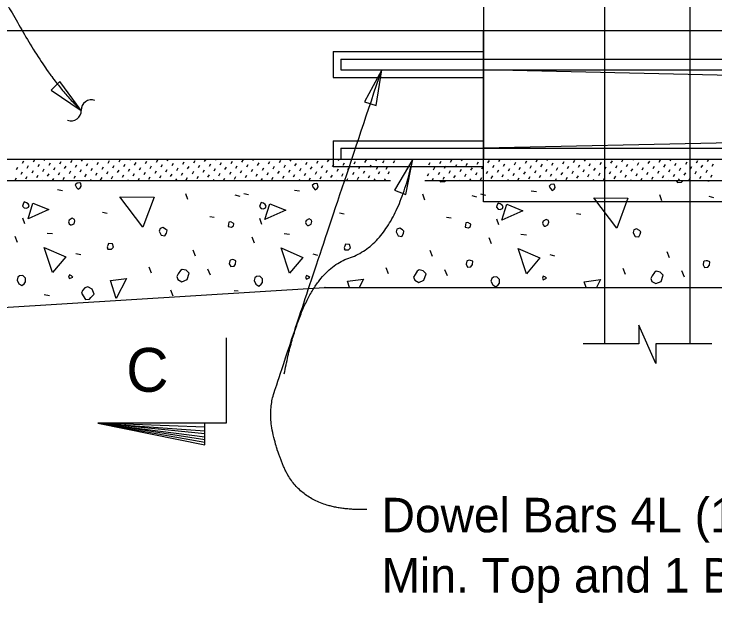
# Model space of a CAD drawing. Extents: x 1.5 to 68.7, y 0 to 31.
# Drawn here: x 28.879 to 32.972, y 9.338 to 12.779 of the extents above; entities that cross this region are included whole.
import ezdxf

# ---------------------------------------------------------------- set-up
doc = ezdxf.new("R2010")
doc.units = 0
for name, color, linetype in [('Dimension', 7, 'Continuous'), ('Miscellaneous', 7, 'Continuous'), ('Rebar', 7, 'Continuous'), ('TextStructures', 7, 'Continuous'), ('TrafBarrierConc', 7, 'Continuous')]:
    doc.layers.add(name, color=color, linetype=linetype)

msp = doc.modelspace()

# ---------------------------------------------------------------- linework, layer by layer
at = {"layer": 'Dimension'}
for p, q in [((29.9931, 10.3647), (29.3681, 10.3881)), ((29.3681, 10.3881), (29.9931, 10.3447)), ((29.9931, 10.3264), (29.3681, 10.3881)), ((29.3681, 10.3881), (29.9931, 10.3081)), ((29.9931, 10.2914), (29.3681, 10.3881)), ((29.3681, 10.3881), (29.9931, 10.2781))]:
    msp.add_line(p, q, dxfattribs=at)
for points in [[(31.0259, 12.4528), (30.9264, 12.2665), (30.9933, 12.2442)], [(29.2714, 12.2154), (29.1461, 12.3855), (29.0971, 12.3347)], [(31.2075, 11.932), (31.1012, 11.7494), (31.1672, 11.7246)]]:
    msp.add_lwpolyline(points, close=True, dxfattribs=at)
for points in [[(32.9524, 10.8531), (32.6271, 10.8531), (32.6271, 10.7369), (32.5277, 10.9619), (32.5277, 10.8531), (32.2024, 10.8531)], [(30.1181, 10.8881), (30.1181, 10.3881), (29.3681, 10.3881), (29.9931, 10.2631), (29.9931, 10.3881)]]:
    msp.add_lwpolyline(points, dxfattribs=at)
for centre, start, end in [((29.3316, 12.2178), 70.0924, 181.8197), ((29.2124, 12.214), 250.0924, 1.8197)]:
    msp.add_arc(centre, 0.0596, start, end, dxfattribs=at)
for points in [[(28.4708, 12.9203), (28.7034, 12.864), (28.7449, 13.0099), (29.089, 12.3912), (29.2714, 12.2154)], [(30.9383, 9.8847), (30.5669, 9.8722), (30.3433, 10.3915), (30.4451, 10.7169), (31.0259, 12.4528)], [(30.4572, 10.6771), (30.5703, 11.266), (31.1018, 11.4411), (31.2075, 11.932)]]:
    msp.add_open_spline(points, degree=2, dxfattribs=at)
at = {"layer": 'Miscellaneous'}
for p, q in [((28.9291, 11.907), (28.9372, 11.921)), ((28.9926, 11.9151), (29.0007, 11.9291)), ((29.0561, 11.9232), (29.0612, 11.932)), ((29.0838, 11.8955), (29.0919, 11.9095)), ((29.1196, 11.9313), (29.12, 11.932)), ((29.1473, 11.9036), (29.1554, 11.9176)), ((29.2107, 11.9117), (29.2188, 11.9257)), ((29.2742, 11.9198), (29.2813, 11.932)), ((29.3377, 11.9279), (29.3401, 11.932)), ((29.3654, 11.9002), (29.3735, 11.9142)), ((29.4289, 11.9083), (29.437, 11.9223)), ((29.4924, 11.9164), (29.5005, 11.9304)), ((29.5559, 11.9245), (29.5602, 11.932)), ((29.5836, 11.8968), (29.5917, 11.9108)), ((29.6471, 11.9049), (29.6552, 11.9189)), ((29.7106, 11.913), (29.7187, 11.927)), ((29.7741, 11.9211), (29.7804, 11.932)), ((29.8376, 11.9292), (29.8392, 11.932)), ((29.8653, 11.9015), (29.8734, 11.9155)), ((29.9288, 11.9096), (29.9369, 11.9236)), ((29.9922, 11.9177), (30.0003, 11.9317)), ((30.0557, 11.9258), (30.0593, 11.932)), ((30.0834, 11.8981), (30.0915, 11.9121)), ((30.1469, 11.9062), (30.155, 11.9202)), ((30.2104, 11.9143), (30.2185, 11.9283)), ((30.2739, 11.9224), (30.2794, 11.932)), ((30.3016, 11.8948), (30.3097, 11.9087)), ((30.3374, 11.9306), (30.3382, 11.932)), ((30.3651, 11.9029), (30.3732, 11.9169)), ((30.4286, 11.911), (30.4367, 11.925)), ((30.4921, 11.9191), (30.4996, 11.932)), ((30.5556, 11.9272), (30.5584, 11.932)), ((30.5833, 11.8995), (30.5914, 11.9135)), ((30.6468, 11.9076), (30.6549, 11.9216)), ((30.7103, 11.9157), (30.7184, 11.9297)), ((30.7737, 11.9238), (30.7785, 11.932)), ((30.8014, 11.8961), (30.8095, 11.9101)), ((30.8372, 11.9319), (30.8373, 11.932)), ((30.8649, 11.9042), (30.873, 11.9182)), ((30.9284, 11.9123), (30.9365, 11.9263)), ((30.9919, 11.9204), (30.9986, 11.932)), ((31.0331, 11.9089), (31.0412, 11.9229)), ((31.0554, 11.9285), (31.0574, 11.932)), ((31.0941, 11.9089), (31.1022, 11.9229)), ((31.3013, 11.8974), (31.3094, 11.9114)), ((31.3648, 11.9055), (31.3729, 11.9195)), ((31.4283, 11.9136), (31.4364, 11.9276)), ((31.4918, 11.9217), (31.4977, 11.932)), ((31.5552, 11.9298), (31.5565, 11.932)), ((31.5829, 11.9021), (31.591, 11.9161)), ((31.6464, 11.9102), (31.6545, 11.9242)), ((31.7099, 11.9183), (31.7178, 11.932)), ((31.7734, 11.9264), (31.7766, 11.932)), ((31.8011, 11.8987), (31.8092, 11.9127)), ((31.8646, 11.9068), (31.8727, 11.9208)), ((31.9281, 11.9149), (31.9362, 11.9289)), ((31.9916, 11.923), (31.9968, 11.932)), ((32.0193, 11.8953), (32.0274, 11.9093)), ((32.0551, 11.9311), (32.0556, 11.932)), ((32.0828, 11.9034), (32.0909, 11.9174)), ((32.1463, 11.9115), (32.1544, 11.9255)), ((32.2098, 11.9196), (32.2169, 11.932)), ((32.2733, 11.9278), (32.2757, 11.932)), ((32.301, 11.9001), (32.3091, 11.9141)), ((32.3644, 11.9082), (32.3725, 11.9222)), ((32.4279, 11.9163), (32.436, 11.9303)), ((32.4914, 11.9244), (32.4958, 11.932)), ((32.5191, 11.8967), (32.5272, 11.9107)), ((32.5826, 11.9048), (32.5907, 11.9188)), ((32.6461, 11.9129), (32.6542, 11.9269)), ((32.7096, 11.921), (32.716, 11.932)), ((32.7731, 11.9291), (32.7748, 11.932)), ((32.8008, 11.9014), (32.8089, 11.9154)), ((32.8643, 11.9095), (32.8724, 11.9235)), ((32.9278, 11.9176), (32.9359, 11.9316)), ((28.8933, 11.8712), (28.9014, 11.8852)), ((28.9568, 11.8793), (28.9649, 11.8933)), ((29.0203, 11.8874), (29.0284, 11.9014)), ((29.048, 11.8597), (29.0561, 11.8737)), ((29.1115, 11.8678), (29.1196, 11.8818)), ((29.1749, 11.8759), (29.1831, 11.8899)), ((29.2384, 11.884), (29.2465, 11.898)), ((29.2661, 11.8563), (29.2742, 11.8703)), ((29.3019, 11.8921), (29.31, 11.9061)), ((29.3296, 11.8644), (29.3377, 11.8784)), ((29.3931, 11.8725), (29.4012, 11.8865)), ((29.4566, 11.8806), (29.4647, 11.8946)), ((29.5201, 11.8887), (29.5282, 11.9027)), ((29.5478, 11.861), (29.5559, 11.875)), ((29.6113, 11.8691), (29.6194, 11.8831)), ((29.6748, 11.8772), (29.6829, 11.8912)), ((29.7383, 11.8853), (29.7464, 11.8993)), ((29.766, 11.8576), (29.7741, 11.8716)), ((29.8018, 11.8934), (29.8099, 11.9074)), ((29.8295, 11.8657), (29.8376, 11.8797)), ((29.893, 11.8738), (29.9011, 11.8878)), ((29.9564, 11.8819), (29.9646, 11.8959)), ((29.9841, 11.8542), (29.9922, 11.8682)), ((30.0199, 11.89), (30.028, 11.904)), ((30.0476, 11.8623), (30.0557, 11.8763)), ((30.1111, 11.8704), (30.1192, 11.8844)), ((30.1746, 11.8785), (30.1827, 11.8925)), ((30.2381, 11.8867), (30.2462, 11.9006)), ((30.2658, 11.859), (30.2739, 11.873)), ((30.3293, 11.8671), (30.3374, 11.8811)), ((30.3928, 11.8752), (30.4009, 11.8892)), ((30.4563, 11.8833), (30.4644, 11.8973)), ((30.484, 11.8556), (30.4921, 11.8696)), ((30.5198, 11.8914), (30.5279, 11.9054)), ((30.5475, 11.8637), (30.5556, 11.8777)), ((30.611, 11.8718), (30.6191, 11.8858)), ((30.6745, 11.8799), (30.6826, 11.8939)), ((30.7379, 11.888), (30.7461, 11.902)), ((30.7656, 11.8603), (30.7737, 11.8743)), ((30.8291, 11.8684), (30.8372, 11.8824)), ((30.8926, 11.8765), (30.9007, 11.8905)), ((30.9561, 11.8846), (30.9642, 11.8986)), ((30.9957, 11.8731), (31.0038, 11.8871)), ((31.0515, 11.8731), (31.0596, 11.8871)), ((31.329, 11.8697), (31.3371, 11.8837)), ((31.3925, 11.8778), (31.4006, 11.8918)), ((31.456, 11.8859), (31.4641, 11.8999)), ((31.4837, 11.8582), (31.4918, 11.8722)), ((31.5195, 11.894), (31.5276, 11.908)), ((31.5471, 11.8663), (31.5552, 11.8803)), ((31.6106, 11.8744), (31.6187, 11.8884)), ((31.6741, 11.8825), (31.6822, 11.8965)), ((31.7018, 11.8548), (31.7099, 11.8688)), ((31.7376, 11.8906), (31.7457, 11.9046)), ((31.7653, 11.8629), (31.7734, 11.8769)), ((31.8288, 11.871), (31.8369, 11.885)), ((31.8923, 11.8791), (31.9004, 11.8931)), ((31.9558, 11.8872), (31.9639, 11.9012)), ((31.9835, 11.8595), (31.9916, 11.8735)), ((32.047, 11.8676), (32.0551, 11.8816)), ((32.1105, 11.8757), (32.1186, 11.8897)), ((32.174, 11.8839), (32.1821, 11.8978)), ((32.2017, 11.8562), (32.2098, 11.8702)), ((32.2375, 11.892), (32.2456, 11.9059)), ((32.2652, 11.8643), (32.2733, 11.8783)), ((32.3286, 11.8724), (32.3367, 11.8864)), ((32.3921, 11.8805), (32.4002, 11.8945)), ((32.4556, 11.8886), (32.4637, 11.9026)), ((32.4833, 11.8609), (32.4914, 11.8749)), ((32.5468, 11.869), (32.5549, 11.883)), ((32.6103, 11.8771), (32.6184, 11.8911)), ((32.6738, 11.8852), (32.6819, 11.8992)), ((32.7015, 11.8575), (32.7096, 11.8715)), ((32.7373, 11.8933), (32.7454, 11.9073)), ((32.765, 11.8656), (32.7731, 11.8796)), ((32.8285, 11.8737), (32.8366, 11.8877)), ((32.892, 11.8818), (32.9001, 11.8958)), ((32.9197, 11.8541), (32.9278, 11.8681)), ((32.9555, 11.8899), (32.9636, 11.9039)), ((28.921, 11.8435), (28.9291, 11.8575)), ((28.9487, 11.8158), (28.9568, 11.8298)), ((28.9845, 11.8516), (28.9926, 11.8656)), ((29.0122, 11.8239), (29.0203, 11.8379)), ((29.0757, 11.832), (29.0838, 11.846)), ((29.1392, 11.8401), (29.1473, 11.8541)), ((29.2026, 11.8482), (29.2107, 11.8622)), ((29.2303, 11.8205), (29.2384, 11.8345)), ((29.2938, 11.8286), (29.3019, 11.8426)), ((29.3573, 11.8367), (29.3654, 11.8507)), ((29.4208, 11.8448), (29.4289, 11.8588)), ((29.4485, 11.8171), (29.4566, 11.8311)), ((29.4843, 11.8529), (29.4924, 11.8669)), ((29.512, 11.8252), (29.5201, 11.8392)), ((29.5755, 11.8333), (29.5836, 11.8473)), ((29.639, 11.8414), (29.6471, 11.8554)), ((29.6667, 11.8137), (29.6748, 11.8277)), ((29.7025, 11.8495), (29.7106, 11.8635)), ((29.7302, 11.8218), (29.7383, 11.8358)), ((29.7937, 11.8299), (29.8018, 11.8439)), ((29.8572, 11.838), (29.8653, 11.852)), ((29.9207, 11.8461), (29.9288, 11.8601)), ((29.9483, 11.8184), (29.9564, 11.8324)), ((30.0118, 11.8265), (30.0199, 11.8405)), ((30.0753, 11.8346), (30.0834, 11.8486)), ((30.1388, 11.8428), (30.1469, 11.8567)), ((30.1665, 11.8151), (30.1746, 11.8291)), ((30.2023, 11.8509), (30.2104, 11.8648)), ((30.23, 11.8232), (30.2381, 11.8372)), ((30.2935, 11.8313), (30.3016, 11.8453)), ((30.357, 11.8394), (30.3651, 11.8534)), ((30.4205, 11.8475), (30.4286, 11.8615)), ((30.4482, 11.8198), (30.4563, 11.8338)), ((30.5117, 11.8279), (30.5198, 11.8419)), ((30.5752, 11.836), (30.5833, 11.85)), ((30.6387, 11.8441), (30.6468, 11.8581)), ((30.6664, 11.8164), (30.6745, 11.8304)), ((30.7022, 11.8522), (30.7103, 11.8662)), ((30.7298, 11.8245), (30.7379, 11.8385)), ((30.7933, 11.8326), (30.8014, 11.8466)), ((30.8568, 11.8407), (30.8649, 11.8547)), ((30.8845, 11.813), (30.8926, 11.827)), ((30.9203, 11.8488), (30.9284, 11.8628)), ((30.948, 11.8211), (30.9561, 11.8351)), ((31.0064, 11.8454), (31.0145, 11.8594)), ((31.0636, 11.8454), (31.0717, 11.8594)), ((31.2932, 11.8339), (31.3013, 11.8479)), ((31.3567, 11.842), (31.3648, 11.856)), ((31.3844, 11.8143), (31.3925, 11.8283)), ((31.4202, 11.8501), (31.4283, 11.8641)), ((31.4479, 11.8224), (31.456, 11.8364)), ((31.5113, 11.8305), (31.5195, 11.8445)), ((31.5748, 11.8386), (31.5829, 11.8526)), ((31.6383, 11.8467), (31.6464, 11.8607)), ((31.666, 11.819), (31.6741, 11.833)), ((31.7295, 11.8271), (31.7376, 11.8411)), ((31.793, 11.8352), (31.8011, 11.8492)), ((31.8565, 11.8433), (31.8646, 11.8573)), ((31.8842, 11.8156), (31.8923, 11.8296)), ((31.92, 11.8514), (31.9281, 11.8654)), ((31.9477, 11.8237), (31.9558, 11.8377)), ((32.0112, 11.8319), (32.0193, 11.8458)), ((32.0747, 11.84), (32.0828, 11.8539)), ((32.1382, 11.8481), (32.1463, 11.862)), ((32.1659, 11.8204), (32.174, 11.8344)), ((32.2294, 11.8285), (32.2375, 11.8425)), ((32.2928, 11.8366), (32.301, 11.8506)), ((32.3563, 11.8447), (32.3644, 11.8587)), ((32.384, 11.817), (32.3921, 11.831)), ((32.4198, 11.8528), (32.4279, 11.8668)), ((32.4475, 11.8251), (32.4556, 11.8391)), ((32.511, 11.8332), (32.5191, 11.8472)), ((32.5745, 11.8413), (32.5826, 11.8553)), ((32.6022, 11.8136), (32.6103, 11.8276)), ((32.638, 11.8494), (32.6461, 11.8634)), ((32.6657, 11.8217), (32.6738, 11.8357)), ((32.7292, 11.8298), (32.7373, 11.8438)), ((32.7927, 11.8379), (32.8008, 11.8519)), ((32.8562, 11.846), (32.8643, 11.86)), ((32.8839, 11.8183), (32.892, 11.8323)), ((32.9474, 11.8264), (32.9555, 11.8404)), ((28.8852, 11.8077), (28.8933, 11.8217)), ((29.0461, 11.807), (29.048, 11.8102)), ((29.1049, 11.807), (29.1115, 11.8183)), ((29.1668, 11.8124), (29.1749, 11.8264)), ((29.325, 11.807), (29.3296, 11.8149)), ((29.385, 11.809), (29.3931, 11.823)), ((29.5452, 11.807), (29.5478, 11.8115)), ((29.604, 11.807), (29.6113, 11.8196)), ((29.7653, 11.807), (29.766, 11.8081)), ((29.8241, 11.807), (29.8295, 11.8162)), ((29.8849, 11.8103), (29.893, 11.8243)), ((30.0442, 11.807), (30.0476, 11.8128)), ((30.103, 11.807), (30.1111, 11.8209)), ((30.2644, 11.807), (30.2658, 11.8095)), ((30.3232, 11.807), (30.3293, 11.8176)), ((30.3847, 11.8117), (30.3928, 11.8257)), ((30.5433, 11.807), (30.5475, 11.8142)), ((30.6029, 11.8083), (30.611, 11.8223)), ((30.7634, 11.807), (30.7656, 11.8108)), ((30.8222, 11.807), (30.8291, 11.8189)), ((30.9819, 11.807), (30.9869, 11.8155)), ((30.9836, 11.807), (30.9838, 11.8074)), ((31.0424, 11.807), (31.0473, 11.8155)), ((31.3213, 11.807), (31.329, 11.8202)), ((31.4826, 11.807), (31.4837, 11.8087)), ((31.5414, 11.807), (31.5471, 11.8168)), ((31.6025, 11.8109), (31.6106, 11.8249)), ((31.7616, 11.807), (31.7653, 11.8134)), ((31.8207, 11.8075), (31.8288, 11.8215)), ((31.9817, 11.807), (31.9835, 11.81)), ((32.0405, 11.807), (32.047, 11.8181)), ((32.1024, 11.8123), (32.1105, 11.8263)), ((32.2606, 11.807), (32.2652, 11.8148)), ((32.3205, 11.8089), (32.3286, 11.8229)), ((32.4808, 11.807), (32.4833, 11.8114)), ((32.5396, 11.807), (32.5468, 11.8195)), ((32.7009, 11.807), (32.7015, 11.808)), ((32.7597, 11.807), (32.765, 11.8161)), ((32.8204, 11.8102), (32.8285, 11.8242)), ((29.1327, 11.7539), (29.1628, 11.7486)), ((30.516, 11.7504), (30.5461, 11.7451)), ((31.8993, 11.7469), (31.9294, 11.7416)), ((29.8947, 11.6956), (29.8823, 11.7292)), ((30.1687, 11.7221), (30.1969, 11.7151)), ((30.2204, 11.7314), (30.2486, 11.7243)), ((31.2779, 11.6921), (31.2656, 11.7257)), ((31.5519, 11.7186), (31.5802, 11.7115)), ((31.6036, 11.7279), (31.6319, 11.7208)), ((32.6612, 11.6885), (32.6488, 11.7221)), ((32.9352, 11.7151), (32.9635, 11.708)), ((28.9432, 11.5537), (28.9308, 11.5873)), ((29.3961, 11.6214), (29.4227, 11.6161)), ((30.0219, 11.5966), (30.0484, 11.5913)), ((30.3264, 11.5502), (30.3141, 11.5838)), ((30.7794, 11.6178), (30.8059, 11.6125)), ((31.4052, 11.5931), (31.4317, 11.5878)), ((32.1627, 11.6143), (32.1892, 11.609)), ((31.7097, 11.5467), (31.6973, 11.5803)), ((29.0726, 11.4994), (29.1045, 11.4959)), ((28.9007, 11.4441), (28.8866, 11.4795)), ((30.284, 11.4406), (30.2699, 11.476)), ((30.4559, 11.4959), (30.4877, 11.4923)), ((31.6673, 11.4371), (31.6531, 11.4724)), ((31.8392, 11.4923), (31.871, 11.4888)), ((29.2406, 11.3809), (29.2689, 11.3739)), ((29.9388, 11.365), (29.9247, 11.4004)), ((30.6239, 11.3774), (30.6521, 11.3703)), ((31.3221, 11.3615), (31.308, 11.3969)), ((32.7062, 11.3544), (32.692, 11.3898)), ((32.0071, 11.3739), (32.0354, 11.3668)), ((29.6825, 11.2643), (29.6684, 11.2996)), ((31.0658, 11.2607), (31.0517, 11.2961)), ((30.0259, 11.2532), (30.0118, 11.2886)), ((31.4092, 11.2497), (31.395, 11.285)), ((32.4491, 11.2572), (32.4349, 11.2926)), ((32.7932, 11.2426), (32.7791, 11.278)), ((29.0563, 11.1401), (29.0863, 11.1348)), ((29.808, 11.1317), (29.7957, 11.1653)), ((30.1638, 11.1648), (30.1885, 11.1613))]:
    msp.add_line(p, q, dxfattribs=at)
for points in [[(32.8274, 10.853), (32.8274, 14.5819), (32.3274, 14.5819), (32.3274, 10.853)], [(29.2441, 11.7663), (29.2547, 11.7557), (29.2653, 11.7628), (29.2724, 11.7734), (29.2689, 11.7911), (29.26, 11.7928), (29.2477, 11.7911), (29.237, 11.7805), (29.2441, 11.7663)], [(30.6274, 11.7628), (30.638, 11.7522), (30.6486, 11.7593), (30.6557, 11.7699), (30.6521, 11.7875), (30.6433, 11.7893), (30.6309, 11.7875), (30.6203, 11.7769), (30.6274, 11.7628)], [(31.3644, 11.8069), (31.3699, 11.7981), (31.3928, 11.7999), (31.3998, 11.8069)], [(32.0107, 11.7593), (32.0213, 11.7486), (32.0319, 11.7557), (32.039, 11.7663), (32.0354, 11.784), (32.0266, 11.7858), (32.0142, 11.784), (32.0036, 11.7734), (32.0107, 11.7593)], [(32.7455, 11.8069), (32.7531, 11.7946), (32.7761, 11.7964), (32.785, 11.8052), (32.7866, 11.8069)], [(32.9321, 11.8004), (32.93, 11.8069)], [(32.9355, 11.8069), (32.9321, 11.8004)], [(29.6313, 11.5347), (29.4969, 11.7115), (29.6967, 11.7098), (29.6313, 11.5347)], [(32.3978, 11.5277), (32.2635, 11.7045), (32.4632, 11.7027), (32.3978, 11.5277)], [(28.9396, 11.6466), (28.952, 11.6448), (28.9644, 11.6501), (28.9679, 11.6607), (28.9626, 11.6695), (28.952, 11.6766), (28.9396, 11.6819), (28.9325, 11.6678), (28.929, 11.6572), (28.9396, 11.6466)], [(28.9613, 11.5825), (28.9896, 11.6744), (29.0832, 11.6373), (28.9613, 11.5825)], [(30.3229, 11.643), (30.3353, 11.6413), (30.3476, 11.6466), (30.3512, 11.6572), (30.3459, 11.666), (30.3353, 11.6731), (30.3229, 11.6784), (30.3158, 11.6642), (30.3123, 11.6536), (30.3229, 11.643)], [(30.3446, 11.5789), (30.3728, 11.6709), (30.4665, 11.6337), (30.3446, 11.5789)], [(31.7062, 11.6395), (31.7185, 11.6377), (31.7309, 11.643), (31.7345, 11.6536), (31.7292, 11.6625), (31.7185, 11.6695), (31.7062, 11.6748), (31.6991, 11.6607), (31.6956, 11.6501), (31.7062, 11.6395)], [(31.7278, 11.5754), (31.7561, 11.6673), (31.8498, 11.6302), (31.7278, 11.5754)], [(29.2088, 11.5471), (29.2158, 11.5471), (29.23, 11.5542), (29.2353, 11.5701), (29.2335, 11.5789), (29.2194, 11.586), (29.2017, 11.5754), (29.1982, 11.5648), (29.2017, 11.5542), (29.2088, 11.5471)], [(30.592, 11.5436), (30.5991, 11.5436), (30.6133, 11.5507), (30.6186, 11.5666), (30.6168, 11.5754), (30.6026, 11.5825), (30.585, 11.5719), (30.5814, 11.5613), (30.585, 11.5507), (30.592, 11.5436)], [(30.1298, 11.5383), (30.1492, 11.533), (30.1616, 11.5418), (30.1634, 11.5542), (30.1598, 11.5577), (30.1457, 11.5648), (30.1333, 11.563), (30.1315, 11.5507), (30.1298, 11.5383)], [(31.513, 11.5347), (31.5325, 11.5294), (31.5449, 11.5383), (31.5466, 11.5507), (31.5431, 11.5542), (31.529, 11.5613), (31.5166, 11.5595), (31.5148, 11.5471), (31.513, 11.5347)], [(31.9753, 11.54), (31.9824, 11.54), (31.9965, 11.5471), (32.0018, 11.563), (32.0001, 11.5719), (31.9859, 11.5789), (31.9682, 11.5683), (31.9647, 11.5577), (31.9682, 11.5471), (31.9753, 11.54)], [(29.7303, 11.5029), (29.7391, 11.487), (29.7603, 11.4835), (29.7691, 11.4994), (29.7727, 11.5135), (29.7638, 11.5224), (29.7479, 11.5312), (29.732, 11.5259), (29.7267, 11.51), (29.7303, 11.5029)], [(31.1135, 11.4994), (31.1224, 11.4835), (31.1436, 11.4799), (31.1524, 11.4959), (31.156, 11.51), (31.1471, 11.5188), (31.1312, 11.5277), (31.1153, 11.5224), (31.11, 11.5065), (31.1135, 11.4994)], [(32.4968, 11.4959), (32.5056, 11.4799), (32.5269, 11.4764), (32.5357, 11.4923), (32.5392, 11.5065), (32.5304, 11.5153), (32.5145, 11.5241), (32.4986, 11.5188), (32.4933, 11.5029), (32.4968, 11.4959)], [(29.428, 11.4057), (29.4492, 11.4057), (29.4598, 11.4163), (29.4545, 11.4358), (29.4315, 11.4375), (29.428, 11.4269), (29.4227, 11.4181), (29.428, 11.4057), (29.4244, 11.4092)], [(30.8112, 11.4022), (30.8325, 11.4022), (30.8431, 11.4128), (30.8378, 11.4322), (30.8148, 11.434), (30.8112, 11.4234), (30.8059, 11.4145), (30.8112, 11.4022), (30.8077, 11.4057)], [(29.104, 11.2691), (29.0563, 11.4159), (29.1818, 11.3611), (29.104, 11.2691)], [(30.4873, 11.2656), (30.4396, 11.4123), (30.5651, 11.3575), (30.4873, 11.2656)], [(31.8706, 11.2621), (31.8228, 11.4088), (31.9484, 11.354), (31.8706, 11.2621)], [(30.1355, 11.3204), (30.1444, 11.3045), (30.1638, 11.3063), (30.1726, 11.3186), (30.1744, 11.3381), (30.162, 11.3434), (30.1532, 11.3452), (30.1426, 11.3416), (30.139, 11.3381), (30.1355, 11.3204)], [(31.5188, 11.3169), (31.5276, 11.301), (31.5471, 11.3027), (31.5559, 11.3151), (31.5577, 11.3345), (31.5453, 11.3398), (31.5365, 11.3416), (31.5259, 11.3381), (31.5223, 11.3345), (31.5188, 11.3169)], [(32.9021, 11.3133), (32.9109, 11.2974), (32.9304, 11.2992), (32.9392, 11.3116), (32.941, 11.331), (32.9286, 11.3363), (32.9197, 11.3381), (32.9091, 11.3345), (32.9056, 11.331), (32.9021, 11.3133)], [(29.203, 11.2338), (29.2225, 11.2426), (29.2154, 11.2497), (29.203, 11.255), (29.1977, 11.2426), (29.203, 11.2338)], [(29.8363, 11.2272), (29.8593, 11.2148), (29.8894, 11.2272), (29.9017, 11.2643), (29.884, 11.282), (29.8611, 11.2873), (29.8505, 11.2802), (29.8381, 11.2607), (29.8292, 11.2448), (29.8363, 11.2272)], [(31.2196, 11.2236), (31.2426, 11.2112), (31.2726, 11.2236), (31.285, 11.2607), (31.2673, 11.2784), (31.2443, 11.2837), (31.2337, 11.2767), (31.2214, 11.2572), (31.2125, 11.2413), (31.2196, 11.2236)], [(32.6036, 11.2165), (32.6266, 11.2042), (32.6567, 11.2165), (32.669, 11.2537), (32.6514, 11.2713), (32.6284, 11.2767), (32.6178, 11.2696), (32.6054, 11.2501), (32.5966, 11.2342), (32.6036, 11.2165)], [(28.8972, 11.2249), (28.9078, 11.2037), (28.9255, 11.1931), (28.9396, 11.2037), (28.9467, 11.2143), (28.9467, 11.2356), (28.9308, 11.2515), (28.9113, 11.2497), (28.9025, 11.2409), (28.8972, 11.2249)], [(29.4757, 11.1176), (29.4421, 11.2219), (29.5358, 11.2342), (29.4757, 11.1176)], [(30.2805, 11.2214), (30.2911, 11.2002), (30.3088, 11.1896), (30.3229, 11.2002), (30.33, 11.2108), (30.33, 11.232), (30.3141, 11.2479), (30.2946, 11.2462), (30.2858, 11.2373), (30.2805, 11.2214)], [(30.5863, 11.2302), (30.6057, 11.2391), (30.5987, 11.2462), (30.5863, 11.2515), (30.581, 11.2391), (30.5863, 11.2302)], [(30.8371, 11.1819), (30.8254, 11.2183), (30.9191, 11.2307), (30.894, 11.1819)], [(31.6637, 11.2179), (31.6744, 11.1967), (31.692, 11.1861), (31.7062, 11.1967), (31.7132, 11.2073), (31.7132, 11.2285), (31.6973, 11.2444), (31.6779, 11.2426), (31.6691, 11.2338), (31.6637, 11.2179)], [(31.9696, 11.2267), (31.989, 11.2356), (31.9819, 11.2426), (31.9696, 11.2479), (31.9643, 11.2356), (31.9696, 11.2267)], [(32.2192, 11.1819), (32.2087, 11.2148), (32.3024, 11.2272), (32.2791, 11.1819)], [(29.2737, 11.1489), (29.2967, 11.1118), (29.3197, 11.1136), (29.3285, 11.1224), (29.348, 11.1419), (29.3356, 11.1719), (29.3108, 11.1861), (29.2932, 11.179), (29.279, 11.1648), (29.2737, 11.1489)], [(30.6951, 11.1819), (30.6941, 11.1825), (30.6927, 11.1819)]]:
    msp.add_lwpolyline(points, dxfattribs=at)
at = {"layer": 'Rebar'}
for p, q in [((30.7872, 12.5153), (34.4226, 12.5153)), ((30.7872, 12.5153), (30.7872, 12.4528)), ((30.7872, 12.4528), (34.4226, 12.4528)), ((34.4226, 12.3904), (31.6205, 12.4528)), ((34.4226, 12.0569), (31.6205, 11.9945)), ((30.7872, 11.9945), (34.4226, 11.9945)), ((30.7872, 11.9945), (30.7872, 11.932)), ((30.7872, 11.932), (34.4226, 11.932))]:
    msp.add_line(p, q, dxfattribs=at)
at = {"layer": 'TrafBarrierConc'}
for p, q in [((31.6205, 14.5986), (31.6205, 11.932)), ((25.4726, 12.682), (34.6205, 12.682)), ((31.6205, 11.932), (31.6205, 12.682)), ((31.6205, 12.682), (34.6205, 12.682)), ((30.7427, 12.5598), (30.7427, 12.4084)), ((30.7427, 12.5598), (31.6205, 12.5598)), ((30.7427, 12.4084), (31.6205, 12.4084)), ((30.7427, 12.0389), (30.7427, 11.8875)), ((30.7427, 12.0389), (31.6205, 12.0389)), ((25.4726, 11.932), (31.1267, 11.932)), ((31.3067, 11.932), (36.344, 11.932)), ((30.7427, 11.8875), (31.6205, 11.8875)), ((27.4727, 11.807), (31.0765, 11.807)), ((31.2771, 11.807), (36.344, 11.807)), ((26.6926, 10.9319), (30.6926, 11.1819)), ((30.6926, 11.182), (36.344, 11.182))]:
    msp.add_line(p, q, dxfattribs=at)
msp.add_lwpolyline([(34.6205, 11.932), (34.6205, 11.682), (31.6205, 11.682), (31.6205, 11.932)], dxfattribs=at)

# ---------------------------------------------------------------- texts
at = {"layer": 'Dimension'}
for s, p in [('Dowel Bars 4L (10" Embedment) (Place 3 Bars ', (31.0251, 9.7512)), ('Min. Top and 1 Bar Min. Bottom)', (31.0251, 9.3992))]:
    msp.add_text(s, height=0.2016, dxfattribs=at).set_placement(p)
at = {"layer": 'TextStructures'}
msp.add_text('C', height=0.256, dxfattribs=at).set_placement((29.5344, 10.5723))

doc.saveas('drawing.dxf')
